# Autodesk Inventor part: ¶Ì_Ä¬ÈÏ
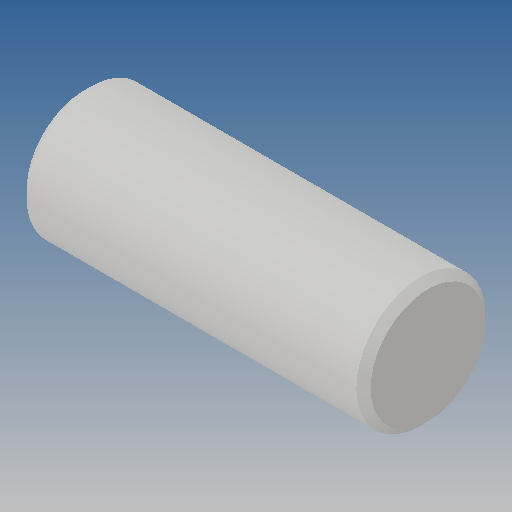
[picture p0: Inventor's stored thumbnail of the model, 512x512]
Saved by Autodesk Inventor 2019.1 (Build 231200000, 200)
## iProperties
Created: 2012-10
Part Number: ¶Ì_Ä¬ÈÏ
Material: Ogólny
Document SubType Name: Modeling
Designer: CADENGINEERING4
Density: 1 g/cm^3
Appearance: Domyślna
Author: CADENGINEERING4
Revision Number: ÈÎºÎ
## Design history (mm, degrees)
feature "NONE"
node "Bryła1"
